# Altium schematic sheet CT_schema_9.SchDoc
size 391 x 238 mm
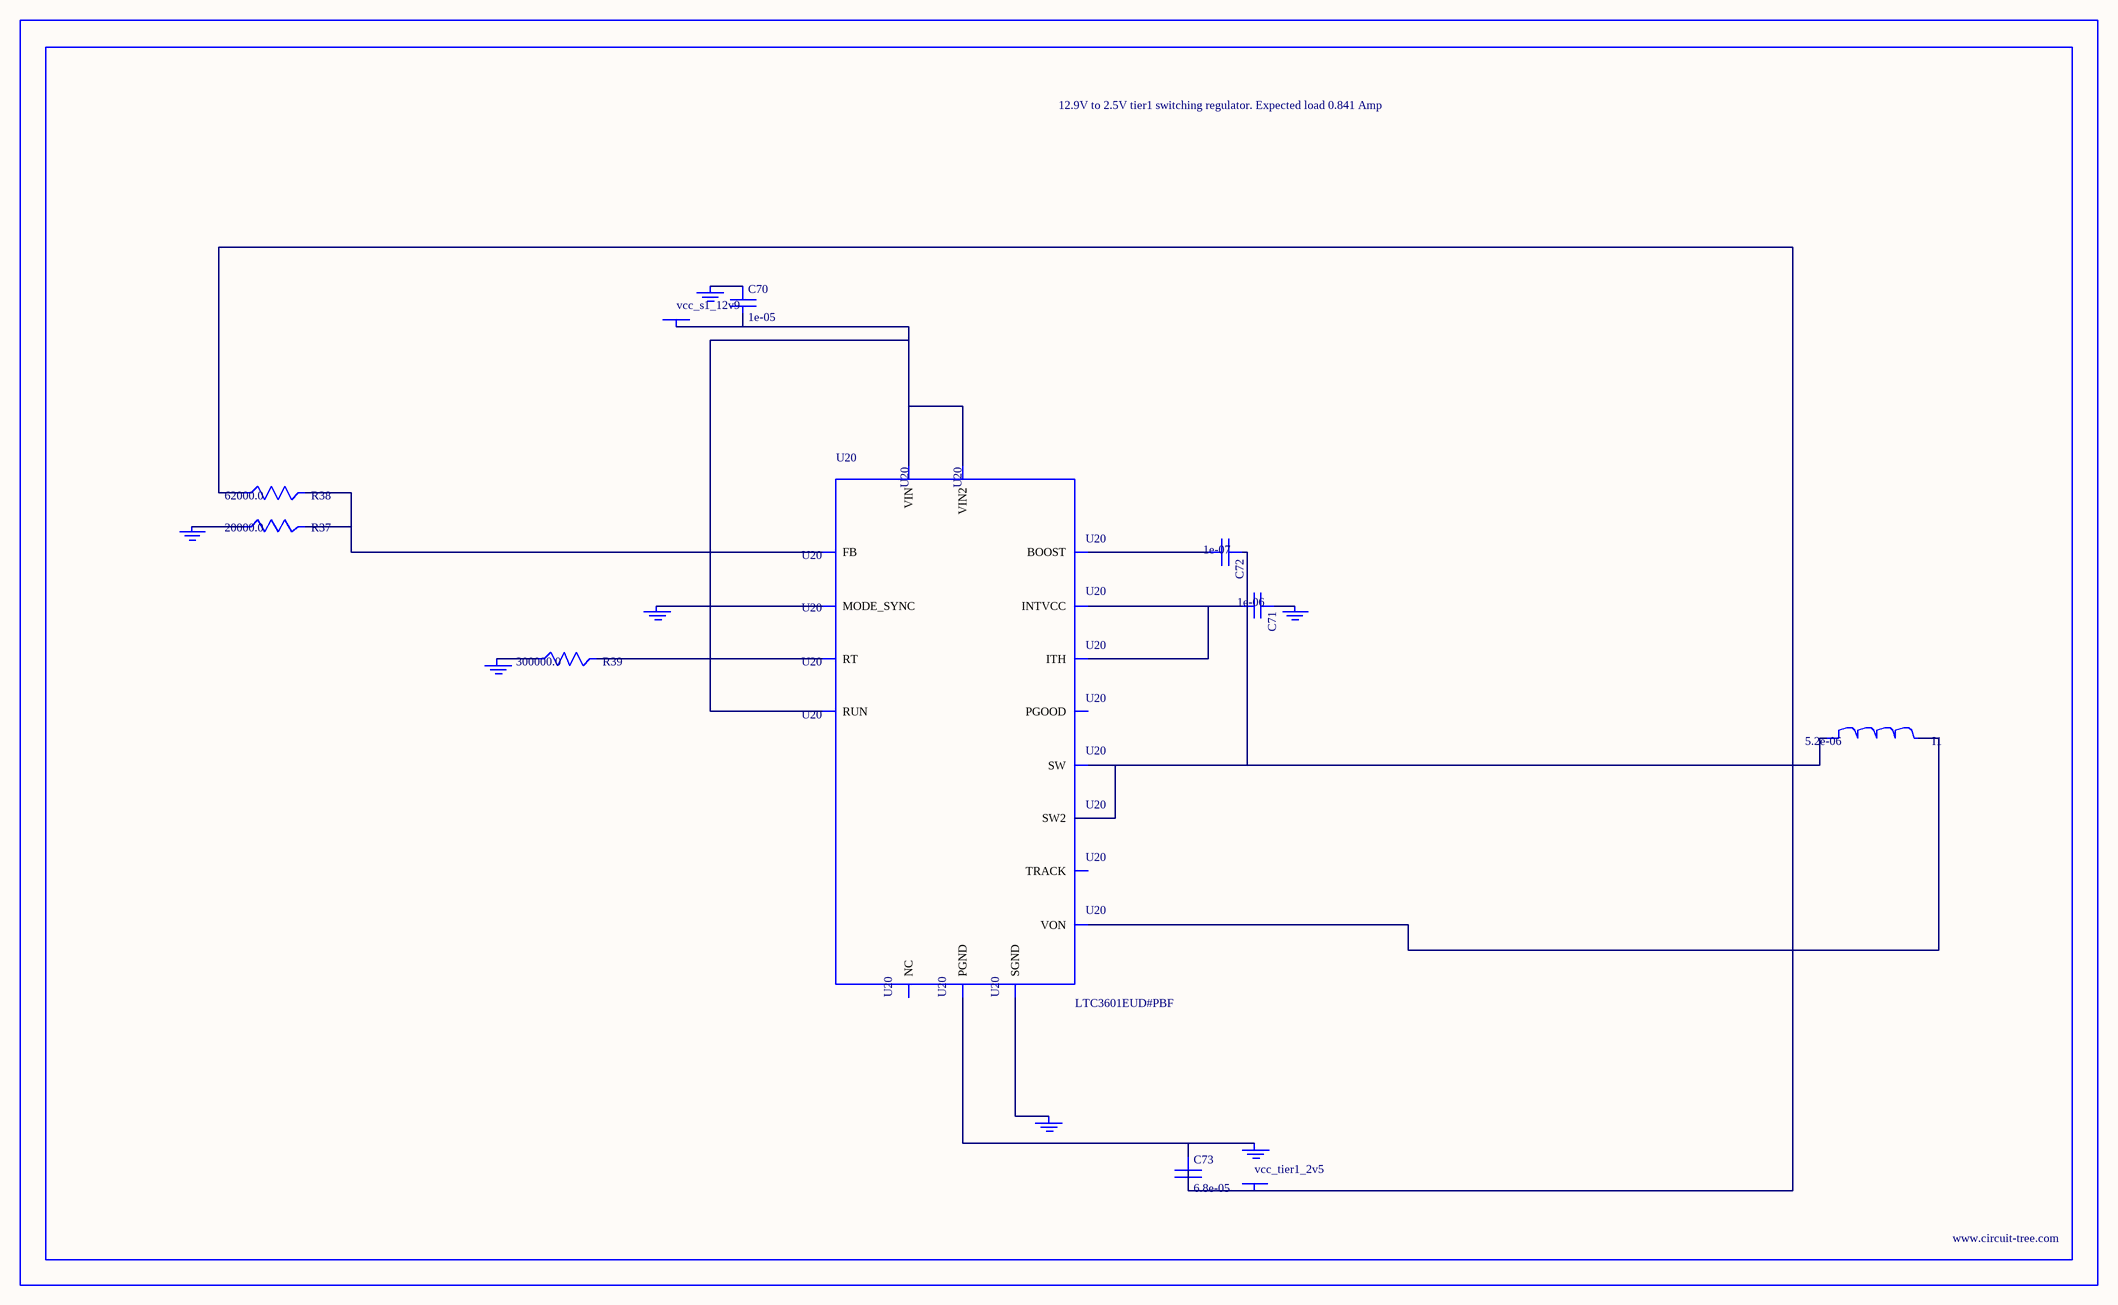
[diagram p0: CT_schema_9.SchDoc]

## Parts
BORDER8  (no value)
C70  1e-05  [C0805]
C71  1e-06  [C0603]
C72  1e-07  [C0402]
C73  6.8e-05  [2220]
GND_INSTANCE_8_0  (no value)
GND_INSTANCE_8_1  (no value)
GND_INSTANCE_8_2  (no value)
GND_INSTANCE_8_3  (no value)
GND_INSTANCE_8_4  (no value)
GND_INSTANCE_8_5  (no value)
GND_INSTANCE_8_6  (no value)
I1  5.2e-06  [DR1040]
POWER_INSTANCE_8_0  vcc_s1_12v9
POWER_INSTANCE_8_1  vcc_tier1_2v5
R37  20000.0  [R0603]
R38  62000.0  [R0603]
R39  300000.0  [R0603]
U20  LTC3601EUD#PBF  [QFN-16_EP]

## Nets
NetC70_1: C70.1 GND_INSTANCE_8_5.0(GND)
NetC70_2: C70.2 POWER_INSTANCE_8_0.0(PWR) U20.14(RUN) U20.15(VIN) U20.16(VIN2)
NetC71_1: C71.1 GND_INSTANCE_8_1.0(GND)
NetC71_2: C71.2 U20.7(INTVCC) U20.12(ITH)
NetC72_1: C72.1 I1.1 U20.3(SW) U20.4(SW2)
NetC72_2: C72.2 U20.6(BOOST)
NetC73_1: C73.1 GND_INSTANCE_8_6.0(GND) U20.17(PGND)
NetC73_2: C73.2 I1.2 POWER_INSTANCE_8_1.0(PWR) R38.1 U20.8(VON)
NetGND_INSTANCE_8_0_0: GND_INSTANCE_8_0.0(GND) U20.1(MODE_SYNC)
NetGND_INSTANCE_8_2_0: GND_INSTANCE_8_2.0(GND) U20.9(SGND)
NetGND_INSTANCE_8_3_0: GND_INSTANCE_8_3.0(GND) R39.1
NetGND_INSTANCE_8_4_0: GND_INSTANCE_8_4.0(GND) R37.1
NetR37_2: R37.2 R38.2 U20.11(FB)
NetR39_2: R39.2 U20.10(RT)

Not connected (* = marked no-connect by the designer): U20 2(PGOOD) 5(NC) 13(TRACK)

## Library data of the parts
BORDER8 = BORDER_PAGE8
C70 = C0805C106K8RACTU
C71 = C0603C105K3RACTU
C72 = C0402C104K3RACTU
C73 = C5750X5R1A686M
GND_INSTANCE_8_0-GND_INSTANCE_8_6 = GND
I1 = DR1040-5R2-R
POWER_INSTANCE_8_0 POWER_INSTANCE_8_1 = PWR
R37 = RC0603JR-0720KL
R38 = RC0603JR-0762KL
R39 = RC0603JR-07300KL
